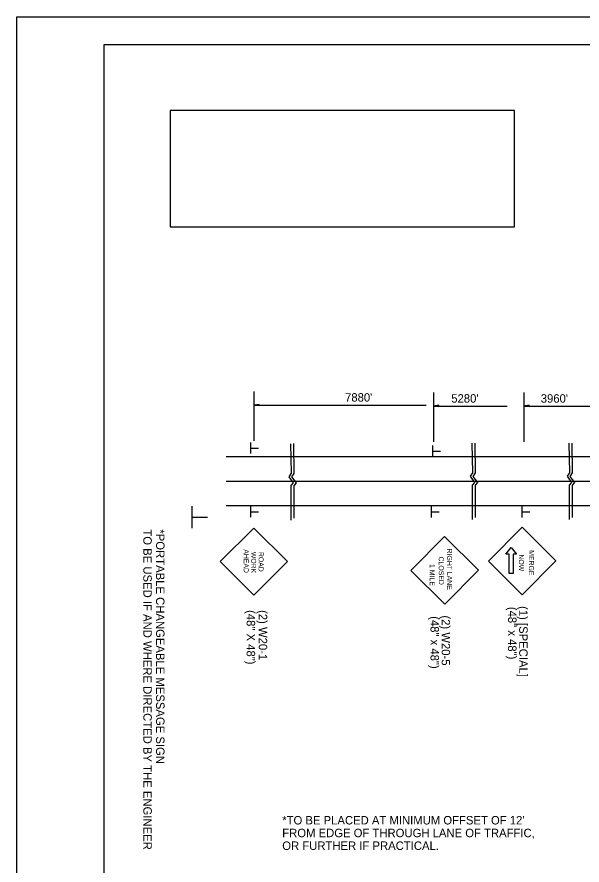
# Model space of a CAD drawing. Extents: x 1374897 to 1375063, y 381144 to 381251.
# Drawn here: x 1374896.6 to 1374936.8, y 381190.7 to 381251 of the extents above; entities that cross this region are included whole.
import ezdxf

# ---------------------------------------------------------------- set-up
doc = ezdxf.new("R2010")
doc.units = 0
for name, color, linetype in [('Default', 7, 'Continuous'), ('R_Border', 7, 'Continuous'), ('R_Draft', 7, 'Continuous'), ('R_No Plot', 7, 'Continuous')]:
    doc.layers.add(name, color=color, linetype=linetype)

msp = doc.modelspace()

# ---------------------------------------------------------------- linework, layer by layer
at = {"layer": 'Default'}
for p, q in [((1374913.414, 381224.337), (1374913.414, 381220.816)), ((1374926.206, 381224.27), (1374926.206, 381220.75)), ((1374932.622, 381224.27), (1374932.622, 381220.75)), ((1374913.789, 381223.414), (1374913.414, 381223.358)), ((1374913.414, 381223.358), (1374925.677, 381223.358)), ((1374913.789, 381223.302), (1374913.414, 381223.358)), ((1374913.789, 381223.405), (1374913.477, 381223.358)), ((1374913.789, 381223.311), (1374913.477, 381223.358)), ((1374913.789, 381223.395), (1374913.541, 381223.358)), ((1374913.789, 381223.321), (1374913.541, 381223.358)), ((1374913.789, 381223.386), (1374913.604, 381223.358)), ((1374913.789, 381223.33), (1374913.604, 381223.358)), ((1374913.789, 381223.376), (1374913.667, 381223.358)), ((1374913.789, 381223.34), (1374913.667, 381223.358)), ((1374913.789, 381223.367), (1374913.73, 381223.358)), ((1374913.789, 381223.349), (1374913.73, 381223.358)), ((1374913.789, 381223.302), (1374913.789, 381223.414)), ((1374926.581, 381223.348), (1374926.206, 381223.291)), ((1374926.581, 381223.338), (1374926.269, 381223.291)), ((1374926.581, 381223.329), (1374926.333, 381223.291)), ((1374926.581, 381223.319), (1374926.396, 381223.291)), ((1374926.581, 381223.235), (1374926.581, 381223.348)), ((1374932.997, 381223.348), (1374932.622, 381223.291)), ((1374932.997, 381223.338), (1374932.685, 381223.291)), ((1374932.997, 381223.329), (1374932.749, 381223.291)), ((1374932.997, 381223.319), (1374932.812, 381223.291)), ((1374932.997, 381223.235), (1374932.997, 381223.348)), ((1374926.206, 381223.291), (1374931.425, 381223.291)), ((1374926.581, 381223.235), (1374926.206, 381223.291)), ((1374926.581, 381223.244), (1374926.269, 381223.291)), ((1374926.581, 381223.254), (1374926.333, 381223.291)), ((1374926.581, 381223.263), (1374926.396, 381223.291)), ((1374926.581, 381223.31), (1374926.459, 381223.291)), ((1374926.581, 381223.273), (1374926.459, 381223.291)), ((1374926.581, 381223.3), (1374926.522, 381223.291)), ((1374926.581, 381223.283), (1374926.522, 381223.291)), ((1374932.622, 381223.291), (1374937.841, 381223.291)), ((1374932.997, 381223.235), (1374932.622, 381223.291)), ((1374932.997, 381223.244), (1374932.685, 381223.291)), ((1374932.997, 381223.254), (1374932.749, 381223.291)), ((1374932.997, 381223.263), (1374932.812, 381223.291)), ((1374932.997, 381223.31), (1374932.875, 381223.291)), ((1374932.997, 381223.273), (1374932.875, 381223.291)), ((1374932.997, 381223.3), (1374932.938, 381223.291)), ((1374932.997, 381223.283), (1374932.938, 381223.291)), ((1374913.206, 381219.914), (1374913.206, 381220.696)), ((1374913.218, 381220.303), (1374913.752, 381220.303)), ((1374926.144, 381219.706), (1374926.144, 381220.488)), ((1374911.462, 381219.7), (1374918.34, 381219.7)), ((1374918.34, 381219.7), (1374921.765, 381219.7)), ((1374921.765, 381219.7), (1374928.427, 381219.7)), ((1374926.156, 381220.095), (1374926.69, 381220.095)), ((1374928.427, 381219.7), (1374935.327, 381219.7)), ((1374935.327, 381219.7), (1374942.721, 381219.7)), ((1374911.462, 381217.961), (1374918.416, 381217.961)), ((1374918.416, 381217.961), (1374922.309, 381217.961)), ((1374922.309, 381217.961), (1374928.427, 381217.961)), ((1374928.427, 381217.961), (1374935.327, 381217.961)), ((1374935.327, 381217.961), (1374942.767, 381217.961)), ((1374909.035, 381214.618), (1374909.035, 381216.183)), ((1374911.462, 381216.223), (1374918.345, 381216.223)), ((1374913.197, 381215.396), (1374913.197, 381216.178)), ((1374918.345, 381216.223), (1374921.77, 381216.223)), ((1374921.77, 381216.223), (1374928.427, 381216.223)), ((1374926.047, 381215.38), (1374926.047, 381216.162)), ((1374928.427, 381216.223), (1374935.327, 381216.223)), ((1374932.507, 381215.374), (1374932.507, 381216.156)), ((1374935.327, 381216.223), (1374942.813, 381216.223)), ((1374913.208, 381215.785), (1374913.742, 381215.785)), ((1374926.059, 381215.769), (1374926.593, 381215.769)), ((1374932.519, 381215.763), (1374933.053, 381215.763)), ((1374909.057, 381215.396), (1374910.126, 381215.396)), ((1374911.029, 381212.232), (1374913.417, 381214.622)), ((1374915.807, 381212.232), (1374913.417, 381214.622)), ((1374930.1, 381212.276), (1374932.501, 381214.686)), ((1374934.909, 381212.284), (1374932.501, 381214.686)), ((1374924.583, 381211.613), (1374926.985, 381214.023)), ((1374929.393, 381211.621), (1374926.985, 381214.023)), ((1374931.35, 381212.761), (1374931.725, 381213.248)), ((1374931.725, 381213.248), (1374932.1, 381212.761)), ((1374931.585, 381212.761), (1374931.35, 381212.761)), ((1374931.585, 381211.382), (1374931.585, 381212.761)), ((1374931.866, 381212.761), (1374931.866, 381211.382)), ((1374932.1, 381212.761), (1374931.866, 381212.761)), ((1374913.417, 381209.841), (1374911.029, 381212.232)), ((1374913.417, 381209.841), (1374915.807, 381212.232)), ((1374932.51, 381209.874), (1374930.1, 381212.276)), ((1374932.51, 381209.874), (1374934.909, 381212.284)), ((1374926.993, 381209.211), (1374924.583, 381211.613)), ((1374926.993, 381209.211), (1374929.393, 381211.621)), ((1374931.866, 381211.382), (1374931.585, 381211.382))]:
    msp.add_line(p, q, dxfattribs=at)
for points in [[(1374916.037, 381220.616), (1374916.069, 381218.512), (1374915.907, 381218.271), (1374916.223, 381217.838), (1374916.057, 381217.638), (1374916.056, 381215.192)], [(1374916.237, 381220.635), (1374916.269, 381218.504), (1374916.107, 381218.263), (1374916.423, 381217.83), (1374916.256, 381217.63), (1374916.256, 381215.333)], [(1374928.931, 381220.649), (1374928.963, 381218.546), (1374928.801, 381218.304), (1374929.117, 381217.871), (1374928.951, 381217.671), (1374928.95, 381215.226)], [(1374929.131, 381220.668), (1374929.163, 381218.537), (1374929.001, 381218.296), (1374929.317, 381217.863), (1374929.151, 381217.663), (1374929.15, 381215.366)], [(1374935.832, 381220.649), (1374935.864, 381218.546), (1374935.702, 381218.304), (1374936.018, 381217.871), (1374935.851, 381217.671), (1374935.851, 381215.226)], [(1374936.031, 381220.668), (1374936.064, 381218.537), (1374935.901, 381218.296), (1374936.218, 381217.863), (1374936.051, 381217.663), (1374936.051, 381215.366)]]:
    msp.add_lwpolyline(points, dxfattribs=at)
at = {"layer": 'R_Border'}
for p, q in [((1374902.775, 381249.01), (1375060.865, 381249.01)), ((1374902.775, 381146.28), (1374902.775, 381249.01))]:
    msp.add_line(p, q, dxfattribs=at)
at = {"layer": 'R_Draft'}
msp.add_lwpolyline([(1374907.469, 381236.046), (1374931.957, 381236.046), (1374931.957, 381244.309), (1374907.469, 381244.309)], close=True, dxfattribs=at)
at = {"layer": 'R_No Plot'}
msp.add_line((1374896.575, 381250.958), (1375063.241, 381250.958), dxfattribs=at)
for points in [[(1374896.571, 381250.958), (1375063.241, 381250.958), (1375063.241, 381144.289), (1374896.571, 381144.289)], [(1375019.735, 381249.01), (1375029.545, 381249.01), (1375029.545, 381244.07), (1375037.601, 381244.07), (1375049.201, 381244.07), (1375049.201, 381231.904), (1375060.865, 381231.904), (1375060.865, 381146.28), (1374902.775, 381146.28), (1374902.775, 381249.01)]]:
    msp.add_lwpolyline(points, close=True, dxfattribs=at)

# ---------------------------------------------------------------- texts
at = {"layer": 'Default'}
for s, p in [("7880'", (1374919.908, 381223.611)), ("5280'", (1374927.459, 381223.538)), ("3960'", (1374933.826, 381223.536))]:
    msp.add_text(s, height=0.6, dxfattribs=at).set_placement(p)
for s, height, rotation, p in [('TO BE USED IF AND WHERE DIRECTED BY THE ENGINEER', 0.6, 270, (1374905.559, 381214.526)), ('*PORTABLE CHANGEABLE MESSAGE SIGN', 0.6, 270, (1374906.464, 381214.526)), (' AHEAD', 0.3522, 270.00057, (1374912.701, 381213.244)), ('RIGHT LANE', 0.3544, 270.10045, (1374927.163, 381213.166)), ('WORK', 0.352, 270.00004, (1374913.229, 381212.929)), ('ROAD', 0.3521, 270.00045, (1374913.758, 381212.922)), ('CLOSED', 0.3543, 270.10034, (1374926.574, 381212.594)), ('NOW', 0.3543, 270.10034, (1374932.272, 381212.749)), ('MERGE', 0.3544, 270.10045, (1374932.981, 381213.042)), ('1 MILE', 0.3567, 270.00057, (1374925.933, 381212.064)), ('(48" x 48")', 0.6, 270, (1374931.502, 381209.021)), ('(1) [SPECIAL]', 0.6, 270, (1374932.292, 381209.075)), ('(48" X 48")', 0.6, 270, (1374912.912, 381208.79)), ('(2) W20-1', 0.6, 270, (1374913.768, 381208.79)), ('(48" x 48")', 0.6, 270, (1374925.985, 381208.358)), ('(2) W20-5', 0.6, 270, (1374926.775, 381208.411)), ("*TO BE PLACED AT MINIMUM OFFSET OF 12'", 0.6, 360, (1374915.439, 381193.549)), ('FROM EDGE OF THROUGH LANE OF TRAFFIC,', 0.6, 360, (1374915.439, 381192.644)), ('OR FURTHER IF PRACTICAL.', 0.6, 360, (1374915.439, 381191.739))]:
    msp.add_text(s, height=height, rotation=rotation, dxfattribs=at).set_placement(p)

doc.saveas('drawing.dxf')
